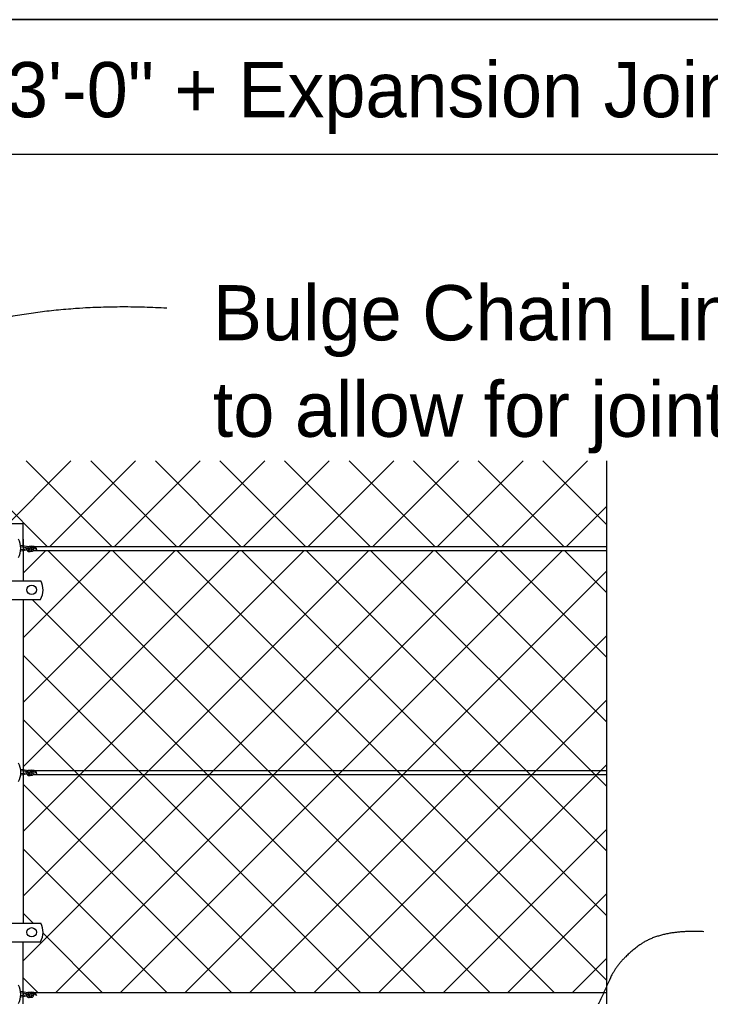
# Model space of a CAD drawing. Extents: x 0 to 41.2, y 0 to 26.
# Drawn here: x 28.834 to 31.356, y 22.394 to 25.96 of the extents above; entities that cross this region are included whole.
import ezdxf

# ---------------------------------------------------------------- set-up
doc = ezdxf.new("R2010")
doc.units = 0
for name, color, linetype in [('ActivePts-ConstElements', 7, 'Continuous'), ('Dimension', 7, 'Continuous'), ('Miscellaneous', 7, 'Continuous'), ('Miscellaneous1', 7, 'Continuous'), ('SteelMisc', 7, 'Continuous'), ('TextStructures', 7, 'Continuous')]:
    doc.layers.add(name, color=color, linetype=linetype)

msp = doc.modelspace()

# ---------------------------------------------------------------- linework, layer by layer
at = {"layer": 'ActivePts-ConstElements'}
msp.add_lwpolyline([(0, 0), (41.2106, 0), (41.2106, 25.96), (0, 25.96)], close=True, dxfattribs=at)
at = {"layer": 'Dimension'}
msp.add_line((25.6609, 25.4682), (35.6727, 25.4682), dxfattribs=at)
msp.add_lwpolyline([(30.9762, 24.349), (30.9762, 21.1819), (31.0795, 21.1819), (30.9762, 21.1369), (30.8729, 21.0919), (30.9762, 21.0919), (30.9762, 20.1983)], dxfattribs=at)
for points in [[(29.3712, 24.906), (28.9427, 24.9313), (28.2117, 24.7126), (27.9092, 24.1238), (27.7412, 22.6169)], [(31.3313, 22.6303), (31.1747, 22.6384), (31.0168, 22.5231), (30.9598, 22.3905), (30.866, 22.2085), (30.5227, 21.5216)]]:
    msp.add_open_spline(points, degree=2, dxfattribs=at)
at = {"layer": 'Miscellaneous'}
for p, q in [((28.7357, 24.0631), (29.0217, 24.349)), ((28.8582, 24.349), (29.1707, 24.0365)), ((28.9448, 24.0365), (29.2574, 24.349)), ((29.0939, 24.349), (29.4064, 24.0365)), ((29.1805, 24.0365), (29.4931, 24.349)), ((29.3296, 24.349), (29.6421, 24.0365)), ((29.4162, 24.0365), (29.7288, 24.349)), ((29.5653, 24.349), (29.8778, 24.0365)), ((29.6519, 24.0365), (29.9645, 24.349)), ((29.801, 24.349), (30.1135, 24.0365)), ((29.8876, 24.0365), (30.2002, 24.349)), ((30.0367, 24.349), (30.3492, 24.0365)), ((30.1233, 24.0365), (30.4359, 24.349)), ((30.2724, 24.349), (30.5849, 24.0365)), ((30.359, 24.0365), (30.6716, 24.349)), ((30.5081, 24.349), (30.8206, 24.0365)), ((30.5947, 24.0365), (30.9073, 24.349)), ((30.7438, 24.349), (30.9762, 24.1166)), ((28.7221, 24.2494), (28.935, 24.0365)), ((30.8304, 24.0365), (30.9762, 24.1823)), ((28.8471, 22.5246), (30.3443, 24.0218)), ((28.8471, 22.7603), (30.1086, 24.0218)), ((28.8471, 22.996), (29.8729, 24.0218)), ((28.8471, 23.2317), (29.6372, 24.0218)), ((28.8471, 23.4674), (29.4015, 24.0218)), ((28.8471, 23.7031), (29.1658, 24.0218)), ((28.8471, 23.9388), (28.9301, 24.0218)), ((28.937, 24.0218), (30.5501, 22.4086)), ((28.9669, 22.4086), (30.58, 24.0218)), ((29.1727, 24.0218), (30.7858, 22.4086)), ((29.2026, 22.4086), (30.8157, 24.0218)), ((29.4084, 24.0218), (30.9762, 22.4539)), ((29.6441, 24.0218), (30.9762, 22.6896)), ((29.8798, 24.0218), (30.9762, 22.9253)), ((30.1155, 24.0218), (30.9762, 23.161)), ((30.3512, 24.0218), (30.9762, 23.3967)), ((30.5869, 24.0218), (30.9762, 23.6324)), ((30.8226, 24.0218), (30.9762, 23.8681)), ((29.4383, 22.4086), (30.9762, 23.9466)), ((28.8797, 23.8433), (30.3144, 22.4086)), ((29.674, 22.4086), (30.9762, 23.7109)), ((28.8471, 23.6402), (30.0787, 22.4086)), ((29.9097, 22.4086), (30.9762, 23.4752)), ((28.8471, 23.4045), (29.843, 22.4086)), ((30.1454, 22.4086), (30.9762, 23.2395)), ((28.8471, 23.1688), (29.6073, 22.4086)), ((30.3811, 22.4086), (30.9762, 23.0038)), ((28.8471, 22.9331), (29.3716, 22.4086)), ((30.6168, 22.4086), (30.9762, 22.768)), ((28.8471, 22.6974), (28.8836, 22.6609)), ((28.9196, 22.6249), (29.1359, 22.4086)), ((30.8525, 22.4086), (30.9762, 22.5323)), ((28.8471, 22.4617), (28.9002, 22.4086))]:
    msp.add_line(p, q, dxfattribs=at)
at = {"layer": 'Miscellaneous1'}
msp.add_lwpolyline([(0, 25.96), (41.2106, 25.96), (41.2106, 0), (0, 0)], close=True, dxfattribs=at)
at = {"layer": 'SteelMisc'}
for p, q in [((28.7846, 24.1198), (28.8471, 24.1198)), ((28.8471, 24.0396), (28.8471, 24.1198)), ((28.8375, 24.0412), (28.8668, 24.0366)), ((28.8376, 24.0412), (28.8669, 24.0366)), ((28.8381, 24.0362), (28.8642, 24.0321)), ((28.8382, 24.0362), (28.8643, 24.0321)), ((28.8471, 24.0636), (28.8471, 23.9109)), ((28.8855, 24.0365), (30.9761, 24.0365)), ((28.838, 24.0207), (28.8717, 24.0264)), ((28.8381, 24.0207), (28.8718, 24.0264)), ((28.8384, 24.0255), (28.8683, 24.0304)), ((28.8385, 24.0255), (28.8684, 24.0304)), ((28.8471, 24.0347), (28.8471, 24.0269)), ((28.8841, 24.0218), (30.9761, 24.0218)), ((28.4206, 23.9109), (28.9116, 23.9109)), ((28.4206, 23.8433), (28.9109, 23.8433)), ((28.8471, 23.8433), (28.8471, 22.6609)), ((28.8377, 23.2237), (28.8669, 23.2191)), ((28.8378, 23.2237), (28.8671, 23.2191)), ((28.8383, 23.2187), (28.8643, 23.2146)), ((28.8384, 23.2187), (28.8644, 23.2146)), ((28.8472, 23.2172), (28.8472, 23.2094)), ((28.8856, 23.219), (30.9763, 23.219)), ((28.8382, 23.2033), (28.8718, 23.2089)), ((28.8383, 23.2033), (28.8719, 23.2089)), ((28.8386, 23.2081), (28.8685, 23.213)), ((28.8387, 23.2081), (28.8686, 23.213)), ((28.8843, 23.2043), (30.9763, 23.2043)), ((28.8471, 22.9552), (28.8471, 22.7653)), ((28.4206, 22.6609), (28.9116, 22.6609)), ((28.4206, 22.5933), (28.9109, 22.5933)), ((28.8471, 21.4109), (28.8471, 22.5933)), ((28.8376, 22.4133), (28.8642, 22.4089)), ((28.8381, 22.3929), (28.8719, 22.3985)), ((28.8382, 22.4083), (28.8641, 22.4041)), ((28.8385, 22.3977), (28.8687, 22.4026)), ((28.8471, 22.4069), (28.8471, 22.399)), ((28.8854, 22.4086), (30.9761, 22.4086))]:
    msp.add_line(p, q, dxfattribs=at)
for centre, major_axis, ratio, start_param, end_param in [((28.7609, 24.03), (0.0776, 0), 0.957868, 5.803915, 6.752041), ((28.8654, 24.0274), (0.0115, -0.0041), 0.737732, 5.08821, 8.212701), ((28.871, 24.0283), (-0.00872, 0), 0.957868, 2.1008, 4.992926), ((28.8776, 24.0288), (-0.00872, 0), 0.957868, 3.323334, 4.992926), ((28.8823, 24.0233), (-0.0142, 0), 0.957868, 3.141593, 4.79635), ((28.8693, 24.0267), (-0.0095, 0), 0.957868, 5.673972, 6.052579), ((28.8693, 24.0267), (-0.0095, 0), 0.957868, 0.252467, 1.271421), ((28.8634, 24.0225), (0.00982, 0), 0.957868, 0.655696, 1.505671), ((28.8688, 24.025), (0.00301, 0), 0.957868, 3.28349, 5.170635), ((28.8694, 24.0272), (-0.00453, 0), 0.957868, 5.149727, 5.551998), ((28.8666, 24.0259), (0.00527, 0), 0.957868, 5.058829, 7.342751), ((28.8688, 24.025), (0.00301, 0), 0.957868, 0.004594, 0.141897), ((28.8771, 24.0278), (0.00944, 0), 0.957868, 4.316497, 6.557353), ((28.8776, 24.0288), (-0.00503, 0), 0.92697, 1.780895, 4.712389), ((28.8743, 24.0082), (0.0274, 0), 0.957868, 0.628521, 1.149654), ((28.842, 23.8778), (0.0776, 0), 0.957868, 5.801244, 6.745158), ((28.7611, 23.2125), (0.0776, 0), 0.957868, 5.803915, 6.752041), ((28.8655, 23.2099), (0.0115, -0.0041), 0.737732, 5.08821, 8.212701), ((28.8712, 23.2108), (-0.00872, 0), 0.957868, 2.1008, 4.992926), ((28.8777, 23.2113), (-0.00872, 0), 0.957868, 3.323334, 4.992926), ((28.8777, 23.2113), (-0.00503, 0), 0.92697, 1.780895, 4.712389), ((28.8825, 23.2058), (-0.0142, 0), 0.957868, 3.141593, 4.79635), ((28.8695, 23.2092), (-0.0095, 0), 0.957868, 5.673972, 6.052579), ((28.8695, 23.2092), (-0.0095, 0), 0.957868, 0.252467, 1.271421), ((28.8636, 23.205), (0.00982, 0), 0.957868, 0.655696, 1.505671), ((28.8689, 23.2075), (0.00301, 0), 0.957868, 3.28349, 5.170635), ((28.8696, 23.2097), (-0.00453, 0), 0.957868, 5.149727, 5.551998), ((28.8668, 23.2084), (0.00527, 0), 0.957868, 5.058829, 7.342751), ((28.8689, 23.2075), (0.00301, 0), 0.957868, 0.004594, 0.141897), ((28.8773, 23.2104), (0.00944, 0), 0.957868, 4.316497, 6.557353), ((28.8745, 23.1908), (0.0274, 0), 0.957868, 0.628521, 1.149654), ((28.842, 22.6278), (0.0776, 0), 0.957868, 5.801244, 6.745158), ((28.7609, 22.4022), (0.0776, 0), 0.957868, 5.803915, 6.752041), ((28.8693, 22.3989), (-0.0095, 0), 0.957868, 5.62303, 6.01932), ((28.8693, 22.3989), (-0.0095, 0), 0.957868, 0.252467, 1.247174), ((28.8634, 22.3947), (0.00982, 0), 0.957868, 0.636815, 1.505671), ((28.8654, 22.3996), (0.0115, -0.0041), 0.737732, 5.048267, 8.212701), ((28.8688, 22.3971), (0.00301, 0), 0.957868, 3.003465, 5.497792), ((28.8694, 22.3993), (-0.00453, 0), 0.957868, 5.149727, 5.551998), ((28.871, 22.4004), (-0.00872, 0), 0.957868, 2.114937, 5.0803), ((28.8666, 22.398), (0.00527, 0), 0.957868, 5.660961, 6.743457), ((28.8688, 22.3971), (0.00301, 0), 0.957868, 0.004594, 0.483719), ((28.8771, 22.4), (0.00944, 0), 0.957868, 4.319295, 6.652508), ((28.8776, 22.4009), (-0.00872, 0), 0.957868, 3.422117, 5.180096), ((28.8776, 22.4009), (-0.00503, 0), 0.92697, 1.789502, 4.651061), ((28.8823, 22.3954), (-0.0142, 0), 0.957868, 3.175145, 4.85532), ((28.8743, 22.3804), (0.0274, 0), 0.957868, 0.63108, 1.149654)]:
    msp.add_ellipse(centre, major_axis=major_axis, ratio=ratio, start_param=start_param, end_param=end_param, dxfattribs=at)
for centre in [(28.8779, 23.8782), (28.8779, 22.6282)]:
    msp.add_ellipse(centre, major_axis=(-0.0177, 0), ratio=0.957868, dxfattribs=at)

# ---------------------------------------------------------------- texts
at = {"layer": 'Dimension'}
for s, p in [('Bulge Chain Link Fabric', (29.5393, 24.7888)), ('to allow for joint movement', (29.5393, 24.4368))]:
    msp.add_text(s, height=0.2016, dxfattribs=at).set_placement(p)
at = {"layer": 'TextStructures'}
msp.add_text('3\'-0" + Expansion Joint Opening (See Note 2)', height=0.2016, dxfattribs=at).set_placement((28.7879, 25.6033))

doc.saveas('drawing.dxf')
